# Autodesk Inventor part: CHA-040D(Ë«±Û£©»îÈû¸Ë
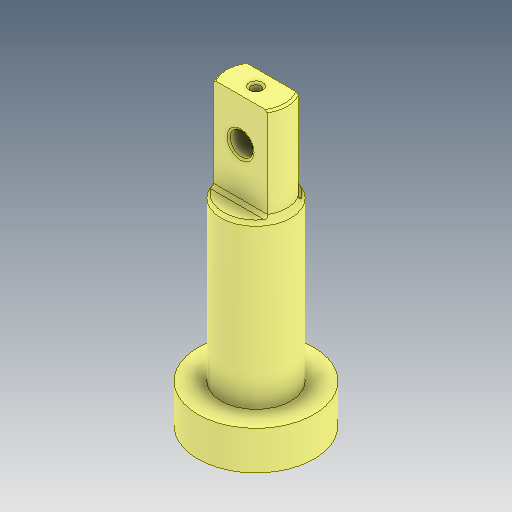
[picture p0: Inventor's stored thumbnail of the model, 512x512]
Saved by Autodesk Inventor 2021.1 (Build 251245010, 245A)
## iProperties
Created: 2021-05
Part Number: CHA-040D(Ë«±Û£©»îÈû¸Ë
Material: Ogólny
Document SubType Name: Modeling
Designer: user
Density: 1 g/cm^3
Appearance: Domyślna
Author: user
Revision Number: ÈÎºÎ
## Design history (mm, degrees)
feature "ÊäÈë1"
node "Bryła1"
